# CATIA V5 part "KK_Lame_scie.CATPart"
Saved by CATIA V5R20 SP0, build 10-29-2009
Part number: Lame_scie
Bounding box of the stored display mesh (mm): x 10 to 12.5, y 130 to 333.571, z -8 to 8
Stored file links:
  G:\Khaled_CFAO_2011\ST2M\ST2M_GR2\aandujar\Khaled\CAD_thinkMOTION\KK_Lame_scie.CATPart
  G:\Khaled_CFAO_2011\ST2M\ST2M_GR2\aandujar\Khaled\CAD_thinkMOTION\KK_Aandujar.CATProduct
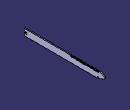
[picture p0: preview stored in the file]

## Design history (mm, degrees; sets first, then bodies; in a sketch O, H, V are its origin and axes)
WSupportSet1: ActiveGrid {3dwsupport RefPoint {point stored without definition}, 3DWOS ({wsupport Support xy-plane, RefPoint {3dwsupport}, GridIn {cartgrid Value 100, Stepbid1 0, Value 100, Stepbid2 0, Direction (1, 0, 0)}, GeometricData ({line type PtDir, Direction (1, 0, 0), Support xy-plane}; {line type PtDir, Direction (0, 1, 0), Support yz-plane})}; {wsupport Support yz-plane, RefPoint {3dwsupport}, GridIn {cartgrid Value 100, Stepbid1 0, Value 100, Stepbid2 0, Direction (0, 1, 0)}, GeometricData ({line type PtDir, Direction (0, 1, 0), Support yz-plane}; {line type PtDir, Direction (0, 0, 1), Support zx-plane})}; {wsupport Support zx-plane, RefPoint {3dwsupport}, GridIn {cartgrid Value 100, Stepbid1 0, Value 100, Stepbid2 0, Direction (0, 0, 1)}, GeometricData ({line type PtDir, Direction (0, 0, 1), Support zx-plane}; {line type PtDir, Direction (1, 0, 0), Support xy-plane})}), GeometricData ({line type PtDir, RefPoint {point stored without definition}, Direction (1, 0, 0), Support xy-plane}; {line type PtDir, RefPoint {point stored without definition}, Direction (0, 1, 0), Support yz-plane}; {line type PtDir, RefPoint {point stored without definition}, Direction (0, 0, 1), Support zx-plane})}
Set1
  Sketch1 on Plane1, origin (12.5, 0, 0), H (0, 1, 0), V (0, 0, 1)
    line L1 (130, 8) -> (130, -8)
    line L2 (130, -8) -> (310.175, -8)
    line L3 (325.0802, -4.6681) -> (332.4282, -1.2103)
    line L4 (317.265, 8) -> (130, 8)
    reference projected line E1 (135, 0) -> (285, 0) from Line1
    reference projected line E2 (135, 0) -> (285, 0) from Line1
    reference projected point E3 (135, 0) from Point2
    arc A1 centre (317.265, -15.6372) radius 23.6372 from (317.265, 8) to (332.8983, 2.0918) cw
    arc A2 centre (310.175, 27.0056) radius 35.0056 from (310.175, -8) to (325.0802, -4.6681) ccw
    arc A3 centre (331.5785, 0.5952) radius 1.9954 from (332.8983, 2.0918) to (332.4282, -1.2103) cw
    distance L2 E1 = 8
    distance L4 E2 = 8
    distance L1 E3 = 5
    radius A1 = 23.6372
    radius A2 = 35.0056
    radius A3 = 1.9954
    vertical: L1 V
    horizontal: L2 H, L4 H
    tangency: A1 L4, A2 L2, A2 L3, A3 A1, A3 L3
Set2
  Plane1 "Plan.Ref5": linked copy from another document
  Point1: linked copy from another document
  Point2: linked copy from another document
  Line1: linked copy from another document
Body1 (main body)
  Pad1: profile Sketch1, direction (-1, 0, 0), length 2.5
  Sketch2 on end face of Pad1, origin (10, 135, 0), H (0, 1, 0), V (0, 0, -1)
    point P1 (0, 0)
    reference projected point E1 (0, 0) from Point2
    coincidence: E1 P1
  Hole1: placed by Sketch2, at (10, 135, 0) direction (1, 0, 0), diameter 5, through (limit type 3)
  Sketch3 on end face of Pad1, origin (10, 0, 0), H (0, -1, 0), V (0, 0, 1)
    point P1 (-317.2643, 8)
    line L1 (-317.2643, 8) -> (-316.5429, 4.5)
    line L2 (-316.5429, 4.5) -> (-316.2429, 4.5)
    line L3 (-316.2429, 4.5) -> (-315.2331, 8)
    point P4 (-315.2331, 8)
    reference projected line E1 (-317.265, 8) -> (-130, 8) from Sketch1.L4
    reference projected line E2 (-317.265, 8) -> (-130, 8) from Sketch1.L4
    reference projected line E3 (-317.265, 8) -> (-130, 8) from edge [end face of Pad1 | face of Pad1 from Sketch1.L4]
    length L2 = 0.3
    distance L2 E3 = 3.5
    horizontal: L2 H
    coincidence: P1 E1, P4 E2
  Pocket1: profile Sketch3, direction (1, 0, 0), through (limit type 3)
  RectPattern1: of Pocket1, direction 1 instances 35, spacing 2, along end face of Pad1 reversed
  Sketch4 on end face of Pad1, origin (10, 0, 0), H (0, -1, 0), V (0, 0, 1)
    spline S1 through (-316.4874, -4.3) (-316.213, -4.7389) (-316.4874, -5.4521) (-315.1155, -4.7389) (-316.4874, -4.3)
    spline S2 through (-316.8601, -4.3132) (-317.2397, -4.6818) (-316.9104, -5.3949) (-318.0628, -5.6692) (-316.8601, -4.3132)
    point P1 (-316.4874, -4.3)
    point P2 (-316.4874, -4.3)
    point P3 (-316.8601, -4.3132)
    point P4 (-316.8601, -4.3132)
    coincidence: P1 P2, P3 P4
  Pocket2: profile Sketch4, direction (1, 0, 0), through (limit type 3)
